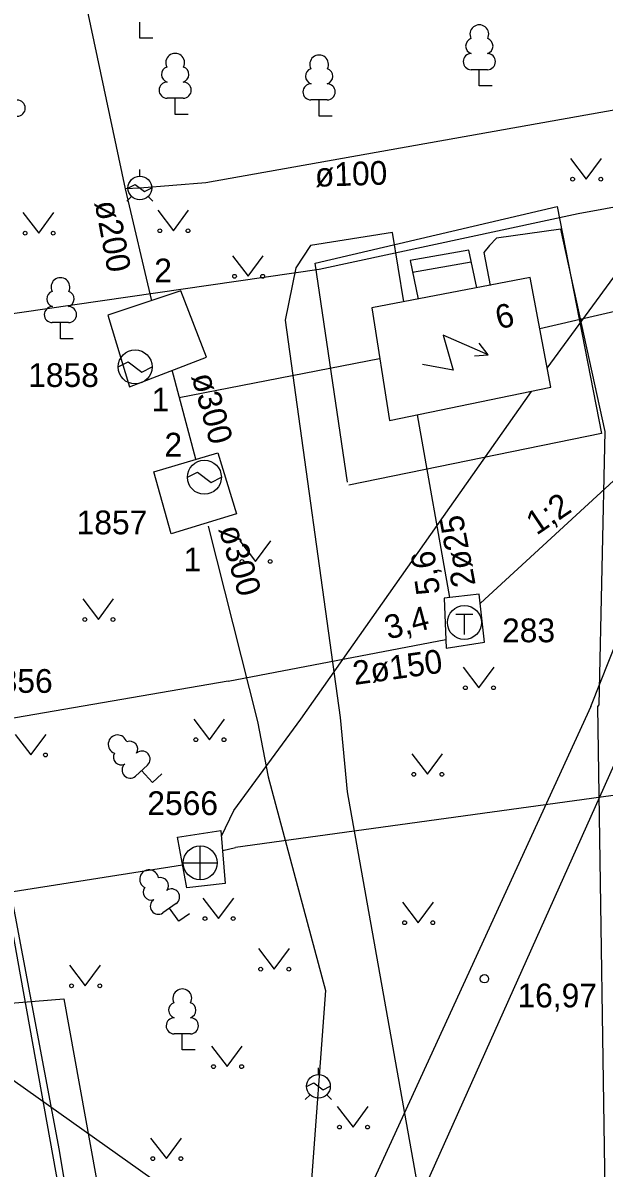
# Model space of a CAD drawing. Extents: x 713540 to 713867, y 6589774 to 6590061.
# Drawn here: x 713720.66 to 713737.79, y 6589807.61 to 6589841.34 of the extents above; entities that cross this region are included whole.
import ezdxf

# ---------------------------------------------------------------- set-up
doc = ezdxf.new("R2010")
doc.units = 0
for name, color, linetype in [('AED', 7, 'Continuous'), ('HALJASTUS', 7, 'Continuous'), ('HOONE', 7, 'Continuous'), ('HOONEDET', 7, 'Continuous'), ('KAEVU_NR', 7, 'Continuous'), ('KKAEV', 7, 'Continuous'), ('KORGUS', 7, 'Continuous'), ('KTRASS', 7, 'Continuous'), ('MPKAABEL', 7, 'Continuous'), ('PUU', 7, 'Continuous'), ('SIKAEV', 7, 'Continuous'), ('SITRASS', 7, 'Continuous'), ('SKTRASS', 7, 'Continuous'), ('TEE', 7, 'Continuous'), ('TKAEV', 7, 'Continuous'), ('TORU NR', 7, 'Continuous'), ('TTRASS', 7, 'Continuous'), ('Слой 1', 7, 'Continuous')]:
    doc.layers.add(name, color=color, linetype=linetype)

msp = doc.modelspace()

# ---------------------------------------------------------------- linework, layer by layer
at = {"layer": 'AED'}
msp.add_lwpolyline([(713730.23, 6589827.82), (713729.27, 6589834.27), (713736.4, 6589835.94), (713737.71, 6589829.25), (713730.27, 6589827.73)], dxfattribs=at)
at = {"layer": 'HALJASTUS'}
for p, q in [((713736.797, 6589837.347), (713737.26, 6589836.74)), ((713737.26, 6589836.74), (713737.706, 6589837.347)), ((713724.637, 6589835.827), (713725.1, 6589835.22)), ((713725.1, 6589835.22), (713725.546, 6589835.827)), ((713720.667, 6589835.757), (713721.13, 6589835.15)), ((713721.13, 6589835.15), (713721.576, 6589835.757)), ((713726.837, 6589834.487), (713727.3, 6589833.88)), ((713727.3, 6589833.88), (713727.746, 6589834.487)), ((713727.057, 6589826.087), (713727.52, 6589825.48)), ((713727.52, 6589825.48), (713727.966, 6589826.087)), ((713722.427, 6589824.377), (713722.89, 6589823.77)), ((713722.89, 6589823.77), (713723.336, 6589824.377)), ((713733.637, 6589822.367), (713734.1, 6589821.76)), ((713734.1, 6589821.76), (713734.546, 6589822.367)), ((713725.697, 6589820.837), (713726.16, 6589820.23)), ((713726.16, 6589820.23), (713726.606, 6589820.837)), ((713720.437, 6589820.387), (713720.9, 6589819.78)), ((713720.9, 6589819.78), (713721.346, 6589820.387)), ((713732.117, 6589819.817), (713732.58, 6589819.21)), ((713732.58, 6589819.21), (713733.026, 6589819.817)), ((713725.967, 6589815.567), (713726.43, 6589814.96)), ((713726.43, 6589814.96), (713726.876, 6589815.567)), ((713731.847, 6589815.447), (713732.31, 6589814.84)), ((713732.31, 6589814.84), (713732.756, 6589815.447)), ((713727.607, 6589814.077), (713728.07, 6589813.47)), ((713728.07, 6589813.47), (713728.516, 6589814.077)), ((713722.037, 6589813.587), (713722.5, 6589812.98)), ((713722.5, 6589812.98), (713722.946, 6589813.587)), ((713726.217, 6589811.207), (713726.68, 6589810.6)), ((713726.68, 6589810.6), (713727.126, 6589811.207)), ((713729.927, 6589809.427), (713730.39, 6589808.82)), ((713730.39, 6589808.82), (713730.836, 6589809.427)), ((713724.427, 6589808.497), (713724.89, 6589807.89)), ((713724.89, 6589807.89), (713725.336, 6589808.497))]:
    msp.add_line(p, q, dxfattribs=at)
for centre in [(713736.859, 6589836.74), (713737.688, 6589836.74), (713720.729, 6589835.15), (713721.558, 6589835.15), (713724.699, 6589835.22), (713725.528, 6589835.22), (713726.899, 6589833.88), (713727.728, 6589833.88), (713727.119, 6589825.48), (713727.948, 6589825.48), (713722.489, 6589823.77), (713723.318, 6589823.77), (713733.699, 6589821.76), (713734.528, 6589821.76), (713725.759, 6589820.23), (713726.588, 6589820.23), (713721.328, 6589819.78), (713732.179, 6589819.21), (713733.008, 6589819.21), (713726.029, 6589814.96), (713726.858, 6589814.96), (713731.909, 6589814.84), (713732.738, 6589814.84), (713727.669, 6589813.47), (713728.498, 6589813.47), (713722.099, 6589812.98), (713722.928, 6589812.98), (713726.279, 6589810.6), (713727.108, 6589810.6), (713729.989, 6589808.82), (713730.818, 6589808.82), (713724.489, 6589807.89), (713725.318, 6589807.89)]:
    msp.add_circle(centre, 0.055, dxfattribs=at)
at = {"layer": 'HOONE'}
for p, q in [((713724.11, 6589836.83), (713724.11, 6589837.027)), ((713723.76, 6589836.478), (713723.971, 6589836.584)), ((713723.971, 6589836.584), (713724.249, 6589836.376)), ((713723.863, 6589836.233), (713723.723, 6589836.093)), ((713724.249, 6589836.376), (713724.46, 6589836.482)), ((713724.357, 6589836.233), (713724.497, 6589836.093)), ((713723.47, 6589831.21), (713723.77, 6589831.36)), ((713723.77, 6589831.36), (713724.17, 6589831.06)), ((713724.17, 6589831.06), (713724.47, 6589831.21)), ((713725.51, 6589827.96), (713725.81, 6589828.11)), ((713725.81, 6589828.11), (713726.21, 6589827.81)), ((713726.21, 6589827.81), (713726.51, 6589827.96)), ((713729.37, 6589810.37), (713729.37, 6589810.567)), ((713729.02, 6589810.018), (713729.231, 6589810.124)), ((713729.231, 6589810.124), (713729.509, 6589809.916)), ((713729.509, 6589809.916), (713729.72, 6589810.022)), ((713729.123, 6589809.773), (713728.983, 6589809.633)), ((713729.617, 6589809.773), (713729.757, 6589809.633))]:
    msp.add_line(p, q, dxfattribs=at)
for points in [[(713736.11, 6589831.17), (713742.62, 6589840.06), (713754.52, 6589857.247)], [(713754.1, 6589850.79), (713749.05, 6589840.73), (713726.05, 6589836.63)], [(713723.69, 6589836.46), (713722.04, 6589844.22)], [(713726.05, 6589836.63), (713724.11, 6589836.48)], [(713724.11, 6589836.48), (713723.69, 6589836.46)], [(713724.46, 6589833.16), (713723.69, 6589836.46)], [(713731.46, 6589829.63), (713736.22, 6589830.61), (713735.61, 6589833.84), (713730.94, 6589832.95), (713731.46, 6589829.63)], [(713740.86, 6589833.48), (713735.89, 6589832.33)], [(713723.17, 6589832.73), (713723.8, 6589830.62), (713726.07, 6589831.5), (713725.32, 6589833.45), (713723.17, 6589832.73)], [(713725.27, 6589830.31), (713731.17, 6589831.46)], [(713725.76, 6589828.49), (713725.06, 6589831.11)], [(713728.85, 6589820.83), (713735.65, 6589830.49)], [(713726.41, 6589828.68), (713726.961, 6589826.881), (713725.03, 6589826.29), (713724.52, 6589828.12), (713726.41, 6589828.68)], [(713726.12, 6589826.52), (713727.58, 6589820.77), (713727.89, 6589819.14), (713729.58, 6589812.84), (713728.69, 6589800.9), (713726.25, 6589779.19)], [(713726.88, 6589818.14), (713728.85, 6589820.83)], [(713726.51, 6589817.39), (713726.88, 6589818.14)], [(713691.059, 6589811.144), (713725.368, 6589816.545)]]:
    msp.add_lwpolyline(points, dxfattribs=at)
for centre, radius in [((713724.11, 6589836.48), 0.35), ((713723.97, 6589831.21), 0.5), ((713726.01, 6589827.96), 0.5), ((713729.37, 6589810.02), 0.35)]:
    msp.add_circle(centre, radius, dxfattribs=at)
at = {"layer": 'HOONEDET'}
for points in [[(713734.04, 6589833.54), (713733.8, 6589834.65), (713732.07, 6589834.34), (713732.31, 6589833.21)], [(713732.14, 6589834), (713733.87, 6589834.31)]]:
    msp.add_lwpolyline(points, dxfattribs=at)
at = {"layer": 'KKAEV'}
for p, q in [((713725.889, 6589816.101), (713725.889, 6589817.101)), ((713725.389, 6589816.601), (713726.389, 6589816.601))]:
    msp.add_line(p, q, dxfattribs=at)
msp.add_circle((713725.889, 6589816.601), 0.5, dxfattribs=at)
at = {"layer": 'KORGUS'}
msp.add_circle((713734.26, 6589813.19), 0.125, dxfattribs=at)
at = {"layer": 'KTRASS'}
msp.add_lwpolyline([(713725.22, 6589817.36), (713726.5, 6589817.56), (713726.62, 6589815.99), (713725.49, 6589815.87), (713725.22, 6589817.36)], dxfattribs=at)
at = {"layer": 'MPKAABEL'}
for points in [[(713733.391, 6589792.128), (713732.429, 6589795.958), (713729.329, 6589801.34), (713725.485, 6589806.569), (713715.308, 6589813.781), (713706.433, 6589812.173), (713706.056, 6589818.501), (713702.321, 6589837.617), (713696.514, 6589869.947), (713694.084, 6589874.558), (713687.448, 6589873.302), (713670.227, 6589869.773), (713666.658, 6589869.039)], [(713731.89, 6589833.13), (713731.55, 6589835.17), (713729.14, 6589834.79), (713728.7, 6589834.13), (713728.39, 6589832.59), (713730.01, 6589820.88)], [(713730.01, 6589820.88), (713730.22, 6589818.69), (713733.842, 6589798.375), (713734.16, 6589796.59), (713734.053, 6589792.116)], [(713633.563, 6589809.916), (713654.618, 6589810.191), (713654.93, 6589810.196), (713666.083, 6589810.341), (713690.526, 6589810.39), (713694.651, 6589811.012), (713704.48, 6589811.17), (713715.623, 6589812.086), (713715.845, 6589812.105), (713721.87, 6589812.6), (713723.29, 6589804.72), (713724.128, 6589800.265), (713724.224, 6589799.756), (713726.25, 6589788.99), (713732.01, 6589789.32)]]:
    msp.add_lwpolyline(points, dxfattribs=at)
at = {"layer": 'PUU'}
for p, q in [((713724.11, 6589840.89), (713724.11, 6589841.365)), ((713724.49, 6589840.89), (713724.11, 6589840.89)), ((713734.35, 6589839.965), (713733.87, 6589839.965)), ((713734.11, 6589839.49), (713734.11, 6589839.965)), ((713734.49, 6589839.49), (713734.11, 6589839.49)), ((713725.39, 6589839.125), (713724.91, 6589839.125)), ((713725.15, 6589838.65), (713725.15, 6589839.125)), ((713729.63, 6589839.075), (713729.15, 6589839.075)), ((713729.39, 6589838.6), (713729.39, 6589839.075)), ((713725.53, 6589838.65), (713725.15, 6589838.65)), ((713729.77, 6589838.6), (713729.39, 6589838.6)), ((713722.01, 6589832.515), (713721.53, 6589832.515)), ((713721.77, 6589832.04), (713721.77, 6589832.515)), ((713722.15, 6589832.04), (713721.77, 6589832.04)), ((713724.337, 6589819.483), (713723.982, 6589819.159)), ((713724.48, 6589818.97), (713724.159, 6589819.321)), ((713724.76, 6589819.226), (713724.48, 6589818.97)), ((713725.181, 6589815.406), (713724.79, 6589815.129)), ((713725.26, 6589814.88), (713724.985, 6589815.268)), ((713725.57, 6589815.1), (713725.26, 6589814.88)), ((713725.6, 6589811.565), (713725.12, 6589811.565)), ((713725.36, 6589811.09), (713725.36, 6589811.565)), ((713725.74, 6589811.09), (713725.36, 6589811.09))]:
    msp.add_line(p, q, dxfattribs=at)
for centre, radius, start, end in [((713734.11, 6589841.01), 0.277, 332.5799, 207.4201), ((713733.94, 6589840.663), 0.233, 109.0217, 253.1415), ((713734.28, 6589840.663), 0.233, 286.8508, 70.9859), ((713725.15, 6589840.17), 0.277, 332.5799, 207.4201), ((713729.39, 6589840.12), 0.277, 332.5799, 207.4201), ((713733.873, 6589840.202), 0.238, 90.0016, 269.3953), ((713734.347, 6589840.202), 0.238, 270.6047, 89.9984), ((713724.98, 6589839.823), 0.233, 109.0217, 253.1415), ((713725.32, 6589839.823), 0.233, 286.8508, 70.9859), ((713729.22, 6589839.773), 0.233, 109.0217, 253.1415), ((713729.56, 6589839.773), 0.233, 286.8508, 70.9859), ((713724.913, 6589839.362), 0.238, 90.0016, 269.3953), ((713725.387, 6589839.362), 0.238, 270.6047, 89.9984), ((713729.153, 6589839.312), 0.238, 90.0016, 269.3953), ((713729.627, 6589839.312), 0.238, 270.6047, 89.9984), ((713720.497, 6589838.832), 0.238, 270.6047, 89.9984), ((713721.77, 6589833.56), 0.277, 332.5799, 207.4201), ((713721.6, 6589833.213), 0.233, 109.0217, 253.1415), ((713721.94, 6589833.213), 0.233, 286.8508, 70.9859), ((713721.533, 6589832.752), 0.238, 90.0016, 269.3953), ((713722.007, 6589832.752), 0.238, 270.6047, 89.9984), ((713723.454, 6589820.092), 0.277, 15.0163, 249.8565), ((713723.814, 6589819.95), 0.233, 329.2872, 113.4223), ((713723.563, 6589819.721), 0.233, 151.4581, 295.5779), ((713724.175, 6589819.656), 0.238, 313.0411, 132.4348), ((713723.824, 6589819.336), 0.238, 132.438, 311.8317), ((713724.381, 6589816.12), 0.277, 7.891, 242.7312), ((713724.721, 6589815.935), 0.233, 322.162, 106.2971), ((713724.443, 6589815.739), 0.233, 144.3329, 288.4527), ((713725.042, 6589815.599), 0.238, 305.9158, 125.3095), ((713724.654, 6589815.324), 0.238, 125.3127, 304.7064), ((713725.36, 6589812.61), 0.277, 332.5799, 207.4201), ((713725.19, 6589812.263), 0.233, 109.0217, 253.1415), ((713725.53, 6589812.263), 0.233, 286.8508, 70.9859), ((713725.123, 6589811.802), 0.238, 90.0016, 269.3953), ((713725.597, 6589811.802), 0.238, 270.6047, 89.9984)]:
    msp.add_arc(centre, radius, start, end, dxfattribs=at)
at = {"layer": 'SITRASS'}
for points in [[(713615.75, 6589870.91), (713621.3, 6589860.3), (713625.233, 6589860.869), (713625.227, 6589860.885), (713640.96, 6589863.23), (713652.708, 6589865.606), (713653.172, 6589865.67), (713666.653, 6589868.422), (713666.793, 6589868.454), (713693.51, 6589873.89), (713696.19, 6589872.18), (713705.63, 6589819.79), (713706.98, 6589814.25), (713714.585, 6589815.353), (713715.248, 6589815.449), (713720.22, 6589816.17), (713721.73, 6589808.13), (713722.95, 6589800.79), (713723.002, 6589800.484), (713723.148, 6589799.687), (713725.92, 6589783.295)], [(713737.91, 6589784.56), (713737.872, 6589797.591), (713737.85, 6589804.99), (713737.6, 6589821.21), (713737.64, 6589821.26), (713737.82, 6589829.31), (713736.51, 6589835.27), (713734.62, 6589835), (713734.41, 6589834.79), (713734.24, 6589834.58), (713734.43, 6589833.61)]]:
    msp.add_lwpolyline(points, dxfattribs=at)
at = {"layer": 'SKTRASS'}
for points in [[(713768.24, 6589822.59), (713755.53, 6589820.99), (713726.93, 6589817.05)], [(713726.55, 6589816.97), (713726.93, 6589817.05)]]:
    msp.add_lwpolyline(points, dxfattribs=at)
at = {"layer": 'TEE'}
for points in [[(713709.501, 6589875.479), (713713.392, 6589853.877), (713718.226, 6589826.424), (713719.066, 6589821.759), (713719.238, 6589820.801), (713720.341, 6589814.674), (713720.518, 6589813.69), (713723.269, 6589798.406), (713724.259, 6589792.837)], [(713737.39, 6589821.21), (713740.69, 6589829.51), (713745.85, 6589841.65), (713746.184, 6589842.396)], [(713737.39, 6589821.21), (713727.69, 6589800.06), (713724.259, 6589792.837)], [(713738.88, 6589821.28), (713731.72, 6589805.3), (713728.981, 6589799.321), (713724.63, 6589790.69)]]:
    msp.add_lwpolyline(points, dxfattribs=at)
at = {"layer": 'TKAEV'}
for p, q in [((713733.42, 6589823.93), (713733.92, 6589823.93)), ((713733.67, 6589823.33), (713733.67, 6589823.93))]:
    msp.add_line(p, q, dxfattribs=at)
msp.add_circle((713733.67, 6589823.68), 0.5, dxfattribs=at)
at = {"layer": 'TORU NR'}
for points in [[(713734.37, 6589831.57), (713733.04, 6589832.15), (713733.34, 6589831.11), (713732.44, 6589831.28)], [(713733.97, 6589831.54), (713734.37, 6589831.57), (713734.11, 6589831.91)]]:
    msp.add_lwpolyline(points, dxfattribs=at)
at = {"layer": 'TTRASS'}
for points in [[(713761.465, 6589855.803), (713760.59, 6589853.78), (713757.7, 6589846.93), (713738.31, 6589828.08), (713734.14, 6589824.25)], [(713733.24, 6589824.42), (713732.29, 6589829.8)], [(713733.13, 6589822.93), (713734.26, 6589823.1), (713734.11, 6589824.52), (713733.07, 6589824.4), (713733.13, 6589822.93)], [(713726.71, 6589821.95), (713733.12, 6589823.18)], [(713726.71, 6589821.95), (713719.87, 6589820.78), (713719.43, 6589820.41)]]:
    msp.add_lwpolyline(points, dxfattribs=at)
at = {"layer": 'Слой 1'}
msp.add_lwpolyline([(713754.51, 6589852.01), (713745.66, 6589837.3), (713737.02, 6589835.72), (713729.39, 6589834.08), (713717.36, 6589832.34), (713707.43, 6589884.34), (713724.46, 6589897.32), (713765.74, 6589876.63)], close=True, dxfattribs=at)

# ---------------------------------------------------------------- texts
at = {"layer": 'KAEVU_NR'}
for s, p in [('1858', (713720.82, 6589830.62)), ('1857', (713722.247, 6589826.28)), ('1856', (713719.46, 6589821.61)), ('2566', (713724.33, 6589818.01))]:
    msp.add_text(s, height=0.7, dxfattribs=at).set_placement(p)
at = {"layer": 'KORGUS'}
msp.add_text('16,97', height=0.7, dxfattribs=at).set_placement((713735.233, 6589812.345))
at = {"layer": 'SIKAEV'}
msp.add_text('283', height=0.7, dxfattribs=at).set_placement((713734.78, 6589823.1))
at = {"layer": 'TORU NR'}
for s, rotation, p in [('ø100', 1.8399, (713729.277, 6589836.515)), ('ø200', 280.6457, (713722.776, 6589836.05)), ('6', 14.4846, (713734.686, 6589832.308)), ('ø300', 285.29, (713725.626, 6589830.935)), ('1;2', 33.938, (713735.795, 6589826.237)), ('2ø25', 100.5825, (713734.005, 6589824.793)), ('ø300', 286.3895, (713726.429, 6589826.444)), ('5,6', 98.0766, (713732.959, 6589824.544)), ('3,4', 14.8466, (713731.426, 6589823.174)), ('2ø150', 8.0259, (713730.431, 6589821.84))]:
    msp.add_text(s, height=0.7, rotation=rotation, dxfattribs=at).set_placement(p)
for s, p in [('2', (713724.534, 6589833.7)), ('1', (713724.458, 6589829.9)), ('2', (713724.834, 6589828.57)), ('1', (713725.398, 6589825.19))]:
    msp.add_text(s, height=0.7, dxfattribs=at).set_placement(p)

doc.saveas('drawing.dxf')
